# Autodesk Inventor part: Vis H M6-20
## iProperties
Shininess: 64.0
Length Units: 11269
Angle Units: 11279
Time Units: 11290
Mass Units: 11283
Length Display Precision: 3
Angle Display Precision: 2
Compacted: True
Part Number: Vis H M6-20
Document SubType Name: Modeling
Created: 2006-01
Material: Par défaut
Designer: Fricot
Density: 0.0
Volumn: 0.0
Area: 0.0
PropertySet Name: Model Information
Control State: 0
Master: False
Checked Out: False
Author: Fricot
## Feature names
1. Base1
